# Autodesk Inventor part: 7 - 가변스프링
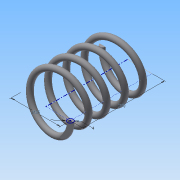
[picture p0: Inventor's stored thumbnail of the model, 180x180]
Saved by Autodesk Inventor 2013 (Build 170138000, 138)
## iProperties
Created: 2015-03
Part Number: 7 - 가변스프링
Material: 강철, 탄소
Document SubType Name: Modeling
Designer: Administrator
Density: 1 g/cm^3
Author: Administrator
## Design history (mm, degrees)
sketch "스케치1"
  geometry: L1 (0, 0)-(17.5, 0); L2 (17.5, 0)-(17.5, 43.5); L3 (17.5, 43.5)-(0, 43.5); L4 (0, 43.5)-(0, 0); C1 r 2 at (17.5, 0)
  constraints: 8 end point, 2 parallel, 1 centre point, 1 coincident, 1 horizontal, 1 perpendicular
  dimensions: "d0" = 4 diameter of C1; "d2" = 35 diameter of L2 L4; "d3" = 43.5 distance of L1.end L2.end (derived)
feature "코일1" pitch "d4" = 10; turns "d6" = 4.5; dims "d5" = 43.5 (= d3), "d7" = 0, angle "d8" = 90 deg, angle "d9" = 90 deg, "d10" = 0, "d11" = 0
node "작업 평면1"
sketch "스케치2"
  geometry: L1 (-19.5, 0)-(-15.5, 0) reference; 1 further point
  constraints: 1 horizontal alignment
extrude "돌출1" cut sketch "스케치2" stored distance "d13" = 10; taper "d14" = 0 deg
node "작업 평면2"
sketch "스케치3"
  geometry: L1 (-19.5, 0)-(-15.5, 0) reference; 1 further point
  constraints: 1 horizontal alignment
extrude "돌출2" cut sketch "스케치3" stored distance "d16" = 10; taper "d17" = 0 deg
node "솔리드1"
node "절단 모서리 투영1"
node "절단 모서리 투영2"
other parameters: "d12" = 0, "d15" = -43.5 (= -d3)
